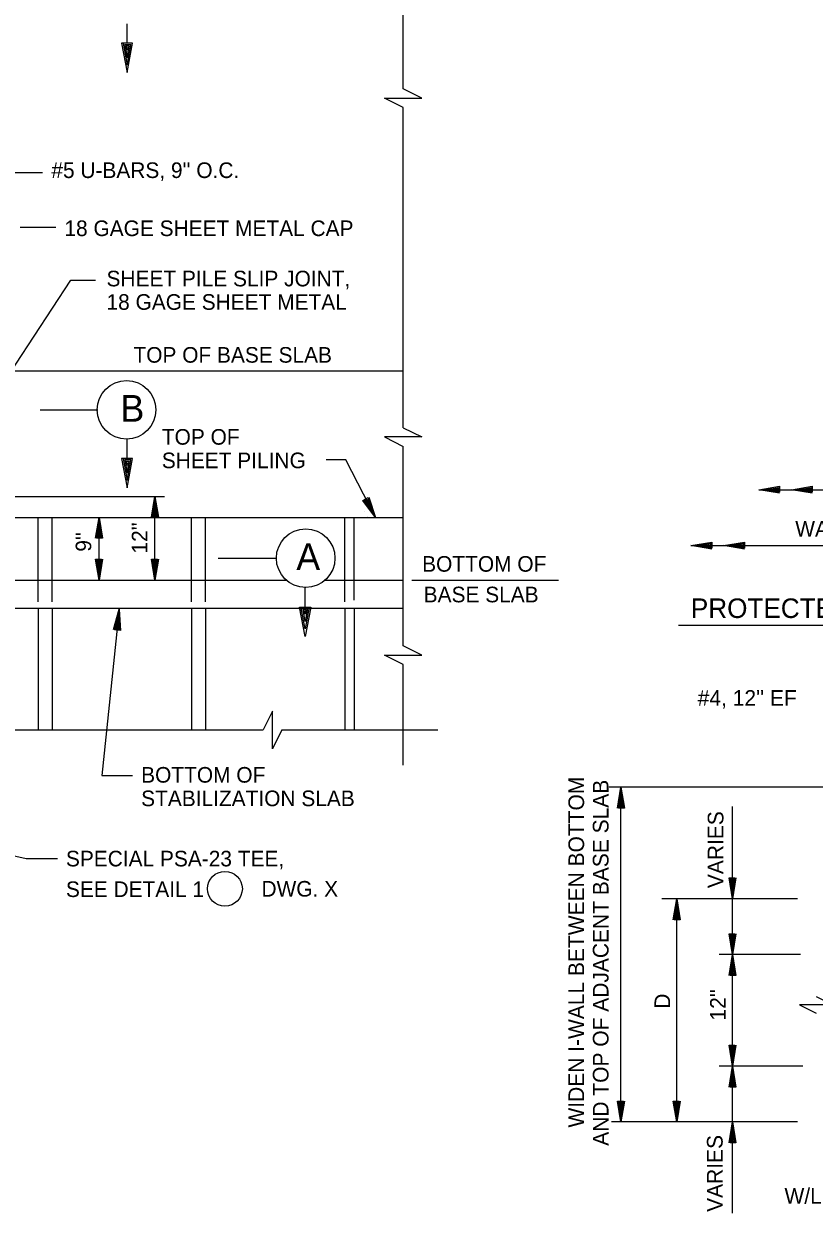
# Model space of a CAD drawing. Extents: x 22369.6 to 22428.3, y 22369.6 to 22415.
# Drawn here: x 22402.68 to 22412.13, y 22388.69 to 22402.9 of the extents above; entities that cross this region are included whole.
import ezdxf

# ---------------------------------------------------------------- set-up
doc = ezdxf.new("R2010")
doc.units = 0
for name, color, linetype in [('Level 1', 7, 'Continuous'), ('Level 10', 7, 'Continuous'), ('Level 2', 7, 'Continuous'), ('Level 3', 7, 'Continuous'), ('Level 4', 7, 'Continuous'), ('Level 7', 7, 'Continuous'), ('Level 8', 7, 'Continuous')]:
    doc.layers.add(name, color=color, linetype=linetype)

msp = doc.modelspace()

# ---------------------------------------------------------------- linework, layer by layer
at = {"layer": 'Level 1'}
for p, q in [((22407.215, 22402.127), (22407.215, 22404.422)), ((22407.215, 22398.077), (22407.215, 22401.902)), ((22402.551, 22401.125), (22402.904, 22401.125)), ((22402.638, 22400.474), (22403.065, 22400.474)), ((22401.468, 22397.133), (22403.245, 22399.842)), ((22403.245, 22399.842), (22403.54, 22399.842)), ((22407.215, 22395.471), (22407.215, 22397.853)), ((22406.53, 22397.694), (22406.295, 22397.694)), ((22406.883, 22397.005), (22406.53, 22397.694)), ((22401.938, 22397.255), (22404.364, 22397.255)), ((22404.248, 22396.255), (22404.248, 22397.255)), ((22404.248, 22397.255), (22404.248, 22397.255)), ((22411.465, 22397.335), (22417.4, 22397.335)), ((22404.248, 22397.186), (22404.248, 22397.186)), ((22403.582, 22396.255), (22403.582, 22397.005)), ((22403.582, 22397.005), (22403.582, 22397.005)), ((22406.754, 22397.072), (22406.754, 22397.072)), ((22406.786, 22397.01), (22406.786, 22397.01)), ((22403.582, 22396.936), (22403.582, 22396.936)), ((22410.654, 22396.669), (22415.511, 22396.669)), ((22403.582, 22396.325), (22403.582, 22396.325)), ((22403.582, 22396.255), (22403.582, 22396.255)), ((22404.248, 22396.325), (22404.248, 22396.325)), ((22404.248, 22396.255), (22404.248, 22396.255)), ((22407.318, 22396.255), (22409.073, 22396.255)), ((22403.82, 22395.907), (22403.613, 22393.922)), ((22403.813, 22395.838), (22403.813, 22395.838)), ((22403.82, 22395.907), (22403.82, 22395.907)), ((22407.215, 22394.044), (22407.215, 22395.246)), ((22399.324, 22394.466), (22405.542, 22394.466)), ((22405.767, 22394.466), (22407.629, 22394.466)), ((22403.613, 22393.922), (22403.981, 22393.922)), ((22415.39, 22393.78), (22409.675, 22393.78)), ((22409.817, 22389.78), (22409.817, 22393.78)), ((22409.817, 22393.78), (22409.817, 22393.78)), ((22409.817, 22393.688), (22409.817, 22393.688)), ((22411.15, 22392.447), (22411.15, 22393.548)), ((22401.36, 22393.23), (22402.709, 22392.927)), ((22402.709, 22392.927), (22403.086, 22392.927)), ((22409.817, 22392.539), (22409.817, 22392.539)), ((22409.817, 22392.447), (22409.817, 22392.447)), ((22409.817, 22392.447), (22409.817, 22392.447)), ((22411.927, 22392.447), (22410.307, 22392.447)), ((22410.484, 22389.78), (22410.484, 22392.447)), ((22411.15, 22391.78), (22411.15, 22392.447)), ((22409.817, 22392.354), (22409.817, 22392.354)), ((22411.963, 22391.78), (22410.991, 22391.78)), ((22411.15, 22390.447), (22411.15, 22391.78)), ((22411.991, 22390.447), (22410.991, 22390.447)), ((22411.15, 22389.78), (22411.15, 22390.447)), ((22409.817, 22389.872), (22409.817, 22389.872)), ((22411.927, 22389.78), (22409.706, 22389.78)), ((22409.817, 22389.78), (22409.817, 22389.78)), ((22411.15, 22388.689), (22411.15, 22389.78))]:
    msp.add_line(p, q, dxfattribs=at)
for points in [[(22407.215, 22401.902), (22406.99, 22402.014), (22407.439, 22402.014), (22407.215, 22402.127)], [(22407.215, 22398.077), (22407.44, 22397.966), (22406.99, 22397.966), (22407.215, 22397.853)], [(22404.207, 22397.006), (22404.248, 22397.255), (22404.29, 22397.006), (22404.219, 22397.006), (22404.248, 22397.186), (22404.276, 22397.017), (22404.231, 22397.017), (22404.248, 22397.119), (22404.263, 22397.027), (22404.244, 22397.027), (22404.248, 22397.05)], [(22406.806, 22397.246), (22406.883, 22397.005), (22406.733, 22397.208), (22406.796, 22397.241), (22406.852, 22397.067), (22406.749, 22397.205), (22406.79, 22397.226), (22406.821, 22397.126), (22406.766, 22397.202), (22406.783, 22397.21), (22406.79, 22397.188)], [(22403.54, 22396.756), (22403.582, 22397.005), (22403.623, 22396.756), (22403.552, 22396.756), (22403.582, 22396.936), (22403.61, 22396.767), (22403.564, 22396.767), (22403.582, 22396.869), (22403.596, 22396.777), (22403.578, 22396.777), (22403.582, 22396.8)], [(22403.623, 22396.505), (22403.582, 22396.255), (22403.54, 22396.505), (22403.611, 22396.505), (22403.582, 22396.325), (22403.554, 22396.494), (22403.599, 22396.494), (22403.582, 22396.391), (22403.567, 22396.483), (22403.586, 22396.483), (22403.582, 22396.461)], [(22404.29, 22396.505), (22404.248, 22396.255), (22404.207, 22396.505), (22404.278, 22396.505), (22404.248, 22396.325), (22404.22, 22396.494), (22404.266, 22396.494), (22404.248, 22396.391), (22404.234, 22396.483), (22404.252, 22396.483), (22404.248, 22396.461)], [(22403.753, 22395.664), (22403.82, 22395.907), (22403.836, 22395.655), (22403.765, 22395.662), (22403.813, 22395.838), (22403.823, 22395.667), (22403.778, 22395.672), (22403.806, 22395.772), (22403.811, 22395.679), (22403.793, 22395.681), (22403.799, 22395.703)], [(22407.215, 22395.246), (22406.99, 22395.358), (22407.439, 22395.358), (22407.215, 22395.471)], [(22405.767, 22394.466), (22405.655, 22394.241), (22405.655, 22394.69), (22405.542, 22394.466)], [(22412.15, 22391.28), (22412.35, 22391.181), (22411.951, 22391.181), (22412.15, 22391.081)]]:
    msp.add_lwpolyline(points, dxfattribs=at)
at = {"layer": 'Level 10'}
for p, q in [((22400.811, 22398.755), (22407.215, 22398.755)), ((22400.811, 22396.255), (22405.818, 22396.255)), ((22406.283, 22396.255), (22407.215, 22396.255)), ((22400.811, 22395.922), (22407.215, 22395.922)), ((22410.506, 22395.718), (22413.733, 22395.718))]:
    msp.add_line(p, q, dxfattribs=at)
at = {"layer": 'Level 2'}
for p, q in [((22400.186, 22397.005), (22407.215, 22397.005)), ((22402.853, 22395.996), (22402.853, 22397.005)), ((22403.019, 22395.996), (22403.019, 22397.005)), ((22404.686, 22395.996), (22404.686, 22397.005)), ((22404.853, 22395.996), (22404.853, 22397.005)), ((22406.519, 22395.996), (22406.519, 22397.005)), ((22406.631, 22396.017), (22406.631, 22397.005))]:
    msp.add_line(p, q, dxfattribs=at)
for points in [[(22411.714, 22397.294), (22411.465, 22397.335), (22411.714, 22397.377), (22411.714, 22397.306), (22411.534, 22397.335), (22411.703, 22397.363), (22411.703, 22397.318), (22411.601, 22397.335), (22411.693, 22397.35), (22411.693, 22397.331), (22411.67, 22397.335)], [(22412.103, 22397.294), (22411.854, 22397.335), (22412.103, 22397.377), (22412.103, 22397.306), (22411.923, 22397.335), (22412.093, 22397.363), (22412.093, 22397.318), (22411.99, 22397.335), (22412.082, 22397.35), (22412.082, 22397.331), (22412.059, 22397.335)], [(22410.903, 22396.627), (22410.654, 22396.669), (22410.903, 22396.71), (22410.903, 22396.639), (22410.723, 22396.669), (22410.893, 22396.697), (22410.893, 22396.651), (22410.79, 22396.669), (22410.882, 22396.683), (22410.882, 22396.665), (22410.859, 22396.669)], [(22411.293, 22396.627), (22411.043, 22396.669), (22411.293, 22396.71), (22411.293, 22396.639), (22411.113, 22396.669), (22411.282, 22396.697), (22411.282, 22396.651), (22411.179, 22396.669), (22411.271, 22396.683), (22411.271, 22396.665), (22411.249, 22396.669)], [(22409.776, 22393.531), (22409.817, 22393.78), (22409.858, 22393.531), (22409.788, 22393.531), (22409.817, 22393.711), (22409.845, 22393.541), (22409.8, 22393.541), (22409.817, 22393.644), (22409.832, 22393.552), (22409.813, 22393.552), (22409.817, 22393.575)], [(22411.192, 22392.696), (22411.15, 22392.447), (22411.109, 22392.696), (22411.18, 22392.696), (22411.15, 22392.516), (22411.122, 22392.685), (22411.168, 22392.685), (22411.15, 22392.583), (22411.136, 22392.675), (22411.154, 22392.675), (22411.15, 22392.652)], [(22410.442, 22392.197), (22410.484, 22392.447), (22410.525, 22392.197), (22410.454, 22392.197), (22410.484, 22392.377), (22410.512, 22392.208), (22410.466, 22392.208), (22410.484, 22392.311), (22410.498, 22392.219), (22410.48, 22392.219), (22410.484, 22392.241)], [(22411.192, 22392.029), (22411.15, 22391.78), (22411.109, 22392.029), (22411.18, 22392.029), (22411.15, 22391.849), (22411.122, 22392.019), (22411.168, 22392.019), (22411.15, 22391.916), (22411.136, 22392.008), (22411.154, 22392.008), (22411.15, 22391.985)], [(22411.109, 22391.531), (22411.15, 22391.78), (22411.192, 22391.531), (22411.121, 22391.531), (22411.15, 22391.711), (22411.178, 22391.541), (22411.133, 22391.541), (22411.15, 22391.644), (22411.165, 22391.552), (22411.146, 22391.552), (22411.15, 22391.575)], [(22411.192, 22390.696), (22411.15, 22390.447), (22411.109, 22390.696), (22411.18, 22390.696), (22411.15, 22390.516), (22411.122, 22390.685), (22411.168, 22390.685), (22411.15, 22390.583), (22411.136, 22390.675), (22411.154, 22390.675), (22411.15, 22390.652)], [(22411.109, 22390.197), (22411.15, 22390.447), (22411.192, 22390.197), (22411.121, 22390.197), (22411.15, 22390.377), (22411.178, 22390.208), (22411.133, 22390.208), (22411.15, 22390.311), (22411.165, 22390.219), (22411.146, 22390.219), (22411.15, 22390.241)], [(22409.858, 22390.029), (22409.817, 22389.78), (22409.776, 22390.029), (22409.846, 22390.029), (22409.817, 22389.849), (22409.789, 22390.019), (22409.834, 22390.019), (22409.817, 22389.916), (22409.802, 22390.008), (22409.821, 22390.008), (22409.817, 22389.985)], [(22410.525, 22390.029), (22410.484, 22389.78), (22410.442, 22390.029), (22410.513, 22390.029), (22410.484, 22389.849), (22410.456, 22390.019), (22410.501, 22390.019), (22410.484, 22389.916), (22410.469, 22390.008), (22410.488, 22390.008), (22410.484, 22389.985)], [(22411.109, 22389.531), (22411.15, 22389.78), (22411.192, 22389.531), (22411.121, 22389.531), (22411.15, 22389.711), (22411.178, 22389.541), (22411.133, 22389.541), (22411.15, 22389.644), (22411.165, 22389.552), (22411.146, 22389.552), (22411.15, 22389.575)]]:
    msp.add_lwpolyline(points, dxfattribs=at)
at = {"layer": 'Level 3'}
for p, q in [((22403.916, 22402.671), (22403.916, 22402.904)), ((22402.879, 22398.291), (22403.567, 22398.291)), ((22403.916, 22397.708), (22403.916, 22397.941)), ((22405.006, 22396.517), (22405.694, 22396.517)), ((22406.044, 22395.933), (22406.044, 22396.167))]:
    msp.add_line(p, q, dxfattribs=at)
for points in [[(22403.867, 22402.671), (22403.85, 22402.671), (22403.916, 22402.321), (22403.982, 22402.671), (22403.867, 22402.671), (22403.915, 22402.41), (22403.962, 22402.654), (22403.887, 22402.654), (22403.915, 22402.498), (22403.941, 22402.638), (22403.906, 22402.638), (22403.915, 22402.588), (22403.922, 22402.621)], [(22403.867, 22397.708), (22403.85, 22397.708), (22403.916, 22397.358), (22403.982, 22397.708), (22403.867, 22397.708), (22403.915, 22397.447), (22403.962, 22397.691), (22403.887, 22397.691), (22403.915, 22397.535), (22403.941, 22397.675), (22403.906, 22397.675), (22403.915, 22397.624), (22403.922, 22397.658)], [(22406.093, 22395.933), (22406.11, 22395.933), (22406.044, 22395.583), (22405.978, 22395.933), (22406.093, 22395.933), (22406.045, 22395.673), (22405.998, 22395.916), (22406.073, 22395.916), (22406.045, 22395.761), (22406.019, 22395.9), (22406.054, 22395.9), (22406.045, 22395.85), (22406.038, 22395.883)]]:
    msp.add_lwpolyline(points, dxfattribs=at)
for centre in [(22403.91, 22398.291), (22406.05, 22396.517)]:
    msp.add_circle(centre, 0.35, dxfattribs=at)
at = {"layer": 'Level 7'}
for p, q in [((22402.853, 22395.922), (22402.853, 22394.466)), ((22403.019, 22395.922), (22403.019, 22394.466)), ((22404.686, 22395.922), (22404.686, 22394.466)), ((22404.853, 22395.922), (22404.853, 22394.466)), ((22406.519, 22395.922), (22406.519, 22394.466)), ((22406.631, 22395.922), (22406.631, 22394.466))]:
    msp.add_line(p, q, dxfattribs=at)
msp.add_circle((22405.085, 22392.567), 0.208, dxfattribs=at)
at = {"layer": 'Level 8'}
for p, q in [((22411.465, 22397.335), (22411.465, 22397.335)), ((22411.534, 22397.335), (22411.534, 22397.335)), ((22412.059, 22397.335), (22412.059, 22397.335)), ((22412.082, 22397.35), (22412.082, 22397.35)), ((22412.082, 22397.331), (22412.082, 22397.331)), ((22412.093, 22397.363), (22412.093, 22397.363)), ((22412.093, 22397.318), (22412.093, 22397.318)), ((22412.103, 22397.377), (22412.103, 22397.377)), ((22412.103, 22397.306), (22412.103, 22397.306)), ((22412.103, 22397.294), (22412.103, 22397.294)), ((22411.271, 22396.683), (22411.271, 22396.683)), ((22411.282, 22396.697), (22411.282, 22396.697)), ((22411.293, 22396.71), (22411.293, 22396.71)), ((22410.654, 22396.669), (22410.654, 22396.669)), ((22410.723, 22396.669), (22410.723, 22396.669)), ((22411.249, 22396.669), (22411.249, 22396.669)), ((22411.271, 22396.665), (22411.271, 22396.665)), ((22411.282, 22396.651), (22411.282, 22396.651)), ((22411.293, 22396.639), (22411.293, 22396.639)), ((22411.293, 22396.627), (22411.293, 22396.627)), ((22409.817, 22393.78), (22409.817, 22393.78)), ((22409.817, 22393.711), (22409.817, 22393.711)), ((22410.484, 22392.447), (22410.484, 22392.447)), ((22411.15, 22392.516), (22411.15, 22392.516)), ((22411.15, 22392.447), (22411.15, 22392.447)), ((22410.484, 22392.377), (22410.484, 22392.377)), ((22411.15, 22391.849), (22411.15, 22391.849)), ((22411.15, 22391.78), (22411.15, 22391.78)), ((22411.15, 22391.78), (22411.15, 22391.78)), ((22411.15, 22391.711), (22411.15, 22391.711)), ((22411.15, 22390.516), (22411.15, 22390.516)), ((22411.15, 22390.447), (22411.15, 22390.447)), ((22411.15, 22390.447), (22411.15, 22390.447)), ((22411.15, 22390.377), (22411.15, 22390.377)), ((22409.817, 22389.849), (22409.817, 22389.849)), ((22409.817, 22389.78), (22409.817, 22389.78)), ((22410.484, 22389.849), (22410.484, 22389.849)), ((22410.484, 22389.78), (22410.484, 22389.78)), ((22411.15, 22389.78), (22411.15, 22389.78)), ((22411.15, 22389.711), (22411.15, 22389.711))]:
    msp.add_line(p, q, dxfattribs=at)

# ---------------------------------------------------------------- texts
at = {"layer": 'Level 10'}
msp.add_text('PROTECTED SIDE', height=0.23333, dxfattribs=at).set_placement((22410.653, 22395.803))
at = {"layer": 'Level 3'}
for s, p in [('B', (22403.836, 22398.148)), ('A', (22405.938, 22396.375))]:
    msp.add_text(s, height=0.32, dxfattribs=at).set_placement(p)
at = {"layer": 'Level 4'}
for s, height, p in [("#5 U-BARS, 9'' O.C.", 0.18667, (22403.011, 22401.061)), ('18 GAGE SHEET METAL CAP', 0.18667, (22403.167, 22400.367)), ('SHEET PILE SLIP JOINT,', 0.18667, (22403.67, 22399.766)), ('18 GAGE SHEET METAL', 0.18667, (22403.67, 22399.486)), ('TOP OF BASE SLAB', 0.18667, (22403.992, 22398.854)), ('TOP OF', 0.1867, (22404.331, 22397.874)), ('SHEET PILING', 0.18667, (22404.331, 22397.593)), ('WALL TEXTURE', 0.1875, (22411.9, 22396.776)), ('BOTTOM OF', 0.1867, (22407.442, 22396.356)), ('BASE SLAB', 0.1867, (22407.46, 22395.99)), ("#4, 12'' EF", 0.1875, (22410.735, 22394.753)), ('BOTTOM OF', 0.1867, (22404.084, 22393.835)), ('STABILIZATION SLAB', 0.18667, (22404.084, 22393.554)), ('SPECIAL PSA-23 TEE,', 0.18667, (22403.185, 22392.834)), ('SEE DETAIL 1', 0.18667, (22403.185, 22392.468)), ('DWG. X', 0.1867, (22405.522, 22392.473)), ('W/L', 0.1875, (22411.772, 22388.802))]:
    msp.add_text(s, height=height, dxfattribs=at).set_placement(p)
for s, height, p in [("12''", 0.1867, (22404.159, 22396.573)), ("9''", 0.1867, (22403.488, 22396.595)), ('WIDEN I-WALL BETWEEN BOTTOM', 0.1875, (22409.377, 22389.713)), ('AND TOP OF ADJACENT BASE SLAB', 0.1875, (22409.669, 22389.495)), ('VARIES', 0.1875, (22411.042, 22392.574)), ('D', 0.187, (22410.405, 22391.133)), ("12''", 0.1875, (22411.07, 22390.992)), ('VARIES', 0.1875, (22411.033, 22388.705))]:
    msp.add_text(s, height=height, rotation=90, dxfattribs=at).set_placement(p)

doc.saveas('drawing.dxf')
